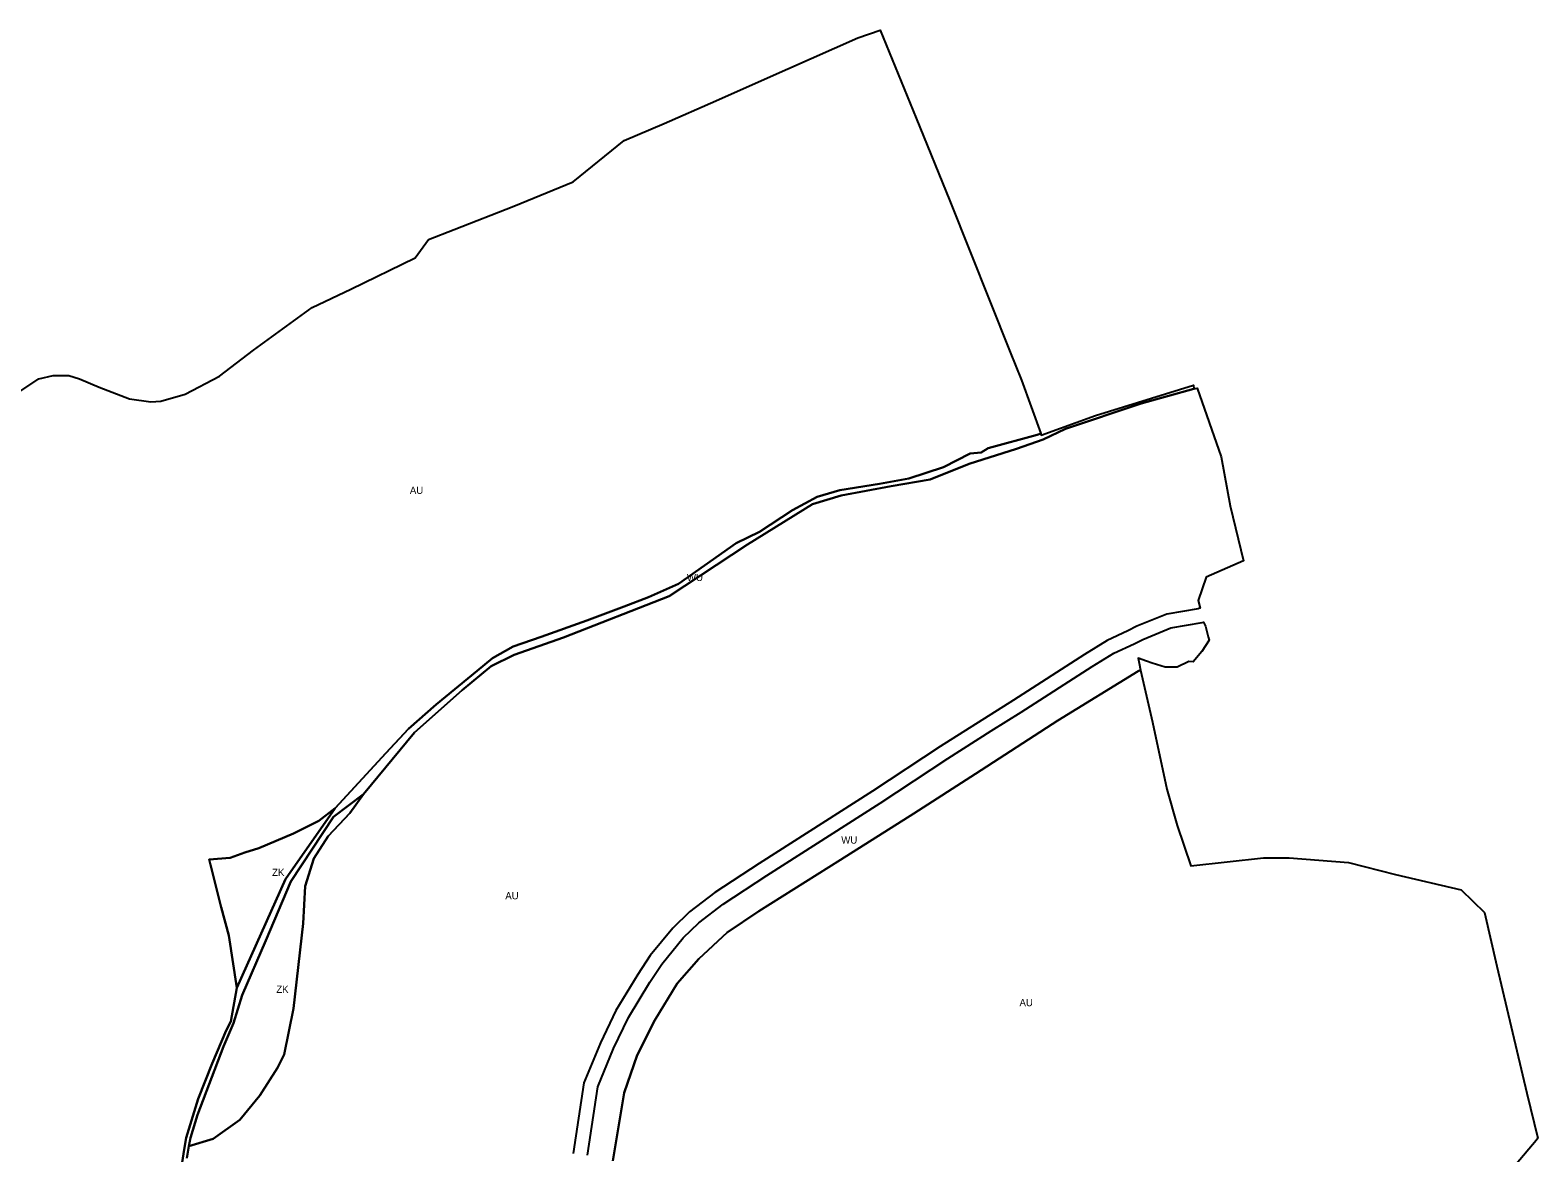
# Model space of a CAD drawing. Extents: x -532067 to -529270, y -1180561 to -1176456.
# Drawn here: x -530875 to -529825, y -1177238 to -1176456 of the extents above; entities that cross this region are included whole.
import ezdxf

# ---------------------------------------------------------------- set-up
doc = ezdxf.new("R2010")
doc.units = 0
for name, color, linetype in [('90630013', 7, 'Continuous'), ('90710013', 7, 'Continuous'), ('90750013', 7, 'Continuous')]:
    doc.layers.add(name, color=color, linetype=linetype)

msp = doc.modelspace()

# ---------------------------------------------------------------- linework, layer by layer
at = {"layer": '90630013'}
for points in [[(-530769.6093, -1177245.67445), (-530767.7953, -1177233.76245), (-530766.7703, -1177227.03145), (-530758.2523, -1177199.84445), (-530748.7013, -1177175.24545), (-530738.8923, -1177152.46045), (-530735.4923, -1177146.14645), (-530731.3133, -1177122.67145), (-530697.3963, -1177046.93945), (-530663.0183, -1176997.58245), (-530643.8413, -1176976.90845), (-530627.5313, -1176959.11045), (-530611.8973, -1176942.11845), (-530592.5173, -1176925.37745), (-530563.9843, -1176901.88745), (-530553.2173, -1176892.97745), (-530538.9513, -1176884.87745), (-530519.3013, -1176878.12745), (-530487.5383, -1176866.78745), (-530461.6973, -1176857.06645), (-530444.7393, -1176850.58645), (-530423.7443, -1176841.13645), (-530383.5223, -1176812.79445), (-530367.2283, -1176805.04145), (-530344.2503, -1176789.95445), (-530327.1203, -1176780.73545), (-530311.2443, -1176775.91545), (-530283.6703, -1176771.51545), (-530263.4073, -1176767.95345), (-530239.2163, -1176760.04345), (-530220.6143, -1176750.45245), (-530212.7903, -1176749.75445), (-530207.9223, -1176746.61545), (-530173.8473, -1176737.54745), (-530171.4453, -1176736.60045), (-530171.1213, -1176737.57445), (-530133.2853, -1176723.87545), (-530065.0993, -1176702.89445), (-530064.7593, -1176705.45345), (-530101.3363, -1176715.63745), (-530154.0823, -1176733.20645), (-530169.6073, -1176740.59345), (-530188.3163, -1176747.18245), (-530221.3573, -1176757.56345), (-530248.5193, -1176768.56745), (-530275.6753, -1176773.14245), (-530310.5013, -1176779.79645), (-530330.4023, -1176785.82645), (-530375.6313, -1176813.86345), (-530430.3583, -1176849.77845), (-530503.9553, -1176878.56345), (-530538.2083, -1176890.67745), (-530554.2373, -1176898.60645), (-530574.4383, -1176915.34545), (-530607.5943, -1176944.85845), (-530643.1113, -1176987.71345), (-530664.1593, -1177003.45845), (-530693.7693, -1177048.54745), (-530711.2503, -1177089.69845), (-530727.6603, -1177127.63045), (-530733.7253, -1177147.31145), (-530740.6923, -1177163.59445), (-530758.7563, -1177211.09645), (-530763.6393, -1177227.01245), (-530764.7433, -1177232.85045), (-530766.3243, -1177241.21445)], [(-530487.1233, -1177239.29545), (-530479.9283, -1177191.48345), (-530469.0433, -1177164.94545), (-530458.6483, -1177143.25745), (-530443.6803, -1177118.65045), (-530435.3643, -1177106.13845), (-530420.3953, -1177087.78645), (-530409.5853, -1177077.36045), (-530392.5373, -1177064.43045), (-530362.1843, -1177044.41145), (-530283.1843, -1176993.94545), (-530236.1413, -1176962.81445), (-530205.9203, -1176943.67145), (-530185.1103, -1176930.64345), (-530135.5223, -1176898.81545), (-530120.4683, -1176889.48845), (-530106.2903, -1176883.02445), (-530100.1863, -1176879.88845), (-530080.8323, -1176871.97345), (-530058.8583, -1176868.24045), (-530057.9473, -1176867.92745), (-530056.7133, -1176870.81645), (-530054.6743, -1176878.21145), (-530054.0393, -1176880.51445), (-530059.1813, -1176888.35445), (-530065.1463, -1176895.57645), (-530068.2323, -1176895.37045), (-530076.4593, -1176899.29145), (-530084.6873, -1176899.29145), (-530093.7383, -1176896.40245), (-530097.7483, -1176895.06145), (-530103.6113, -1176893.10045), (-530102.9433, -1176896.45245), (-530101.9653, -1176901.35445), (-530103.5993, -1176902.12745), (-530159.4063, -1176936.39445), (-530216.7773, -1176973.53945), (-530259.8063, -1177001.26645), (-530310.9193, -1177033.44145), (-530367.8413, -1177069.22645), (-530389.8753, -1177084.10645), (-530409.5093, -1177102.48845), (-530424.5623, -1177119.55645), (-530440.2693, -1177145.16045), (-530452.6443, -1177169.44545), (-530461.6683, -1177195.77945), (-530469.5993, -1177243.23545)]]:
    msp.add_lwpolyline(points, dxfattribs=at)
at = {"layer": '90710013'}
for points in [[(-530747.9973, -1177227.84845), (-530764.7433, -1177232.85045), (-530763.6393, -1177227.01245), (-530758.7563, -1177211.09645), (-530740.6923, -1177163.59445), (-530733.7253, -1177147.31145), (-530727.6603, -1177127.63045), (-530711.2503, -1177089.69845), (-530693.7693, -1177048.54745), (-530664.1593, -1177003.45845), (-530643.1113, -1176987.71345), (-530652.7433, -1177000.95345), (-530667.7273, -1177017.05645), (-530677.7163, -1177032.44445), (-530683.7803, -1177051.76745), (-530685.2073, -1177077.89045), (-530691.9853, -1177136.93445), (-530698.4073, -1177169.14045), (-530703.0453, -1177178.44445), (-530715.5013, -1177197.64345), (-530729.3043, -1177214.61545)], [(-530697.3963, -1177046.93945), (-530731.3133, -1177122.67145), (-530736.9553, -1177086.20145), (-530742.3883, -1177066.49945), (-530749.7013, -1177036.94645), (-530750.6183, -1177033.23945), (-530736.1553, -1177032.04745), (-530725.9253, -1177028.32345), (-530716.0683, -1177025.26745), (-530691.8723, -1177015.20045), (-530674.3093, -1177006.39145), (-530663.0183, -1176997.58245)]]:
    msp.add_lwpolyline(points, close=True, dxfattribs=at)
at = {"layer": '90750013'}
for points in [[(-530895.5463, -1176715.94245), (-530869.4123, -1176698.46445), (-530859.4313, -1176696.09745), (-530848.3603, -1176696.09745), (-530841.1003, -1176698.46445), (-530827.3073, -1176704.29045), (-530806.2153, -1176712.46345), (-530791.3543, -1176714.35645), (-530784.2773, -1176713.88345), (-530767.2933, -1176709.15145), (-530743.4693, -1176696.60945), (-530719.8803, -1176678.38845), (-530678.8353, -1176648.80945), (-530651.9913, -1176635.85945), (-530607.0953, -1176614.09445), (-530597.8583, -1176601.38045), (-530580.0163, -1176594.47545), (-530538.3833, -1176578.04345), (-530497.0913, -1176561.26945), (-530461.6013, -1176532.51345), (-530433.6183, -1176520.53145), (-530397.7873, -1176504.78445), (-530363.8373, -1176489.74845), (-530298.8543, -1176460.89445), (-530283.3013, -1176455.55145), (-530258.2053, -1176516.84145), (-530234.7283, -1176574.37945), (-530192.6343, -1176679.81045), (-530184.8703, -1176699.44345), (-530171.4453, -1176736.60045), (-530173.8473, -1176737.54745), (-530207.9223, -1176746.61545), (-530212.7903, -1176749.75445), (-530220.6143, -1176750.45245), (-530239.2163, -1176760.04345), (-530263.4073, -1176767.95345), (-530283.6703, -1176771.51545), (-530311.2443, -1176775.91545), (-530327.1203, -1176780.73545), (-530344.2503, -1176789.95445), (-530367.2283, -1176805.04145), (-530383.5223, -1176812.79445), (-530423.7443, -1176841.13645), (-530444.7393, -1176850.58645), (-530461.6973, -1176857.06645), (-530487.5383, -1176866.78745), (-530519.3013, -1176878.12745), (-530538.9513, -1176884.87745), (-530553.2173, -1176892.97745), (-530563.9843, -1176901.88745), (-530592.5173, -1176925.37745), (-530611.8973, -1176942.11845), (-530627.5313, -1176959.11045), (-530643.8413, -1176976.90845), (-530663.0183, -1176997.58245), (-530674.3093, -1177006.39145), (-530691.8723, -1177015.20045), (-530716.0683, -1177025.26745), (-530725.9253, -1177028.32345), (-530736.1553, -1177032.04745), (-530750.6183, -1177033.23945), (-530749.7013, -1177036.94645), (-530742.3883, -1177066.49945), (-530736.9553, -1177086.20145), (-530731.3133, -1177122.67145), (-530735.4923, -1177146.14645), (-530738.8923, -1177152.46045), (-530748.7013, -1177175.24545), (-530758.2523, -1177199.84445), (-530766.7703, -1177227.03145), (-530767.7953, -1177233.76245), (-530769.6093, -1177245.67445)], [(-530766.3243, -1177241.21445), (-530764.7433, -1177232.85045), (-530747.9973, -1177227.84845), (-530729.3043, -1177214.61545), (-530715.5013, -1177197.64345), (-530703.0453, -1177178.44445), (-530698.4073, -1177169.14045), (-530691.9853, -1177136.93445), (-530685.2073, -1177077.89045), (-530683.7803, -1177051.76745), (-530677.7163, -1177032.44445), (-530667.7273, -1177017.05645), (-530652.7433, -1177000.95345), (-530643.1113, -1176987.71345), (-530607.5943, -1176944.85845), (-530574.4383, -1176915.34545), (-530554.2373, -1176898.60645), (-530538.2083, -1176890.67745), (-530503.9553, -1176878.56345), (-530430.3583, -1176849.77845), (-530375.6313, -1176813.86345), (-530330.4023, -1176785.82645), (-530310.5013, -1176779.79645), (-530275.6753, -1176773.14245), (-530248.5193, -1176768.56745), (-530221.3573, -1176757.56345), (-530188.3163, -1176747.18245), (-530169.6073, -1176740.59345), (-530154.0823, -1176733.20645), (-530101.3363, -1176715.63745), (-530064.7593, -1176705.45345), (-530062.5483, -1176704.94145), (-530045.7143, -1176752.70345), (-530039.3793, -1176786.88145), (-530030.2523, -1176825.31145), (-530056.2203, -1176836.66045), (-530061.6503, -1176852.86445), (-530060.3443, -1176858.17745), (-530061.3363, -1176858.51845), (-530061.6653, -1176858.57345), (-530083.5953, -1176862.29945), (-530104.3713, -1176870.79545), (-530110.6513, -1176874.02245), (-530125.1943, -1176880.65245), (-530140.8563, -1176890.35645), (-530190.4773, -1176922.20545), (-530241.5673, -1176954.41345), (-530288.6353, -1176985.56145), (-530367.6293, -1177036.02345), (-530398.3183, -1177056.26345), (-530416.1003, -1177069.75045), (-530427.7673, -1177081.00245), (-530443.4223, -1177100.19645), (-530452.1193, -1177113.28245), (-530467.4503, -1177138.48545), (-530478.1853, -1177160.88345), (-530489.6373, -1177188.80345), (-530497.0293, -1177237.92145)], [(-530469.5993, -1177243.23545), (-530461.6683, -1177195.77945), (-530452.6443, -1177169.44545), (-530440.2693, -1177145.16045), (-530424.5623, -1177119.55645), (-530409.5093, -1177102.48845), (-530389.8753, -1177084.10645), (-530367.8413, -1177069.22645), (-530310.9193, -1177033.44145), (-530259.8063, -1177001.26645), (-530216.7773, -1176973.53945), (-530159.4063, -1176936.39445), (-530103.5993, -1176902.12745), (-530101.9653, -1176901.35445), (-530093.6273, -1176937.57745), (-530083.6113, -1176984.13845), (-530076.2833, -1177009.62445), (-530066.8513, -1177037.74145), (-530016.2683, -1177032.10345), (-529998.3363, -1177032.10345), (-529957.1203, -1177035.32545), (-529924.2013, -1177043.64845), (-529878.4353, -1177054.38745), (-529862.1783, -1177070.14845), (-529853.6173, -1177107.44445), (-529832.6783, -1177195.95245), (-529825.1173, -1177227.23945), (-529826.2783, -1177229.04845), (-529840.1833, -1177245.45745)]]:
    msp.add_lwpolyline(points, dxfattribs=at)

# ---------------------------------------------------------------- texts
at = {"layer": '90630013'}
for rotation, p in [(0.00000002, (-530417.8623, -1176839.28481)), (359.99999996, (-530310.3383, -1177022.18371))]:
    msp.add_text('WU', height=5, rotation=rotation, dxfattribs=at).set_placement(p)
at = {"layer": '90710013'}
msp.add_text('ZK', height=5, dxfattribs=at).set_placement((-530706.8183, -1177044.69819))
msp.add_text('ZK', height=5, rotation=359.99999999, dxfattribs=at).set_placement((-530703.9273, -1177126.13186))
at = {"layer": '90750013'}
for rotation, p in [(359.99999998, (-530610.8523, -1176778.56577)), (0.00000002, (-530544.39747, -1177060.96145)), (0.00000003, (-530186.1918, -1177135.43665))]:
    msp.add_text('AU', height=5, rotation=rotation, dxfattribs=at).set_placement(p)

doc.saveas('drawing.dxf')
